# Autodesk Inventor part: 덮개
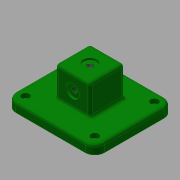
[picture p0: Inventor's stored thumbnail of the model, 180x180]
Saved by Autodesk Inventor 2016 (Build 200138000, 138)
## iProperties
Created: 2017-08
Part Number: 덮개
Material: 알루미늄 6061
Document SubType Name: Modeling
Designer: mduedu
Density: 1 g/cm^3
Appearance: 진녹색
Author: mduedu
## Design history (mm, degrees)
sketch "스케치1"
  geometry: L1 (46, -41)-(-46, -41); L2 (-46, -41)-(-46, 41); L3 (-46, 41)-(46, 41); L4 (46, 41)-(46, -41); 1 further point
  constraints: 8 end point, 2 parallel, 1 horizontal, 1 perpendicular
  dimensions: "d0" = 92 distance of L2.end L3.end; "d2" = 82 distance of L1.end L2.end; "d3" = 41 distance from line of L3 point (0, 0) (= 0.5 x d2); "d4" = 46 distance from line of point (0, 0) L4 (= 0.5 x d0)
extrude "돌출1" new body sketch "스케치1" distance "d5" = 10; taper "d6" = 0 deg
sketch "스케치2"
  geometry: L1 (-18, -18)-(18, -18); L2 (18, -18)-(18, 18); L3 (18, 18)-(-18, 18); L4 (-18, 18)-(-18, -18); L5 (-18, -18)-(18, 18); L6 (18, -18)-(-18, 18); 1 further point
  constraints: 12 end point, 2 midpoint, 2 parallel, 2 perpendicular, 1 horizontal
  dimensions: "d7" = 36 distance of L2.end L3.end
extrude "돌출2" join sketch "스케치2" distance "d9" = 32; taper "d10" = 0 deg
sketch "스케치3"
  geometry: L1 (-26, -26)-(26, -26); L2 (26, -26)-(26, 26); L3 (26, 26)-(-26, 26); L4 (-26, 26)-(-26, -26); L5 (-26, -26)-(26, 26); L6 (26, -26)-(-26, 26); 1 further point
  constraints: 12 end point, 2 midpoint, 2 parallel, 2 perpendicular, 1 horizontal
  dimensions: "d11" = 52 distance of L3.end L2.end
extrude "돌출3" join sketch "스케치3" distance "d12" = 6; taper "d13" = 0 deg
sketch "스케치4"
  geometry: L1 (-17, -17)-(17, -17); L2 (17, -17)-(17, 17); L3 (17, 17)-(-17, 17); L4 (-17, 17)-(-17, -17); L5 (-17, -17)-(17, 17); L6 (17, -17)-(-17, 17); 1 further point
  constraints: 12 end point, 2 midpoint, 2 parallel, 2 perpendicular, 1 horizontal
  dimensions: "d14" = 34 distance of L2.end L3.end
extrude "돌출4" cut sketch "스케치4" distance "d16" = 5; taper "d17" = 0 deg
sketch "스케치5"
  geometry: C1 r 9 at (0, 0); 1 further point
  constraints: 1 centre point, 1 coincident
  dimensions: "d18" = 18 diameter of C1
extrude "돌출5" cut sketch "스케치5" distance "d19" = 34; taper "d20" = 0 deg
sketch "스케치6"
  geometry: 2 further points
  constraints: 1 coincident
hole "구멍1" sketch "스케치6" at (0, 0) diameter "d21" = 5.917; stored, may be unused: countersink angle "d25" = 90 deg, drill point angle "d27" = 118 deg; dims "d22" = 6, "d23" = 14, "d24" = 2, "d26" = 8
sketch "스케치7"
  geometry: L1 (-28, -10)-(64, -10) reference; 3 further points
  constraints: 1 midpoint, 1 vertical alignment
  dimensions: "d47" = 26 distance from line of point (18, 16) L1
hole "구멍2" sketch "스케치7" at (18, 16) diameter "d29" = 5.917; stored, may be unused: countersink angle "d33" = 90 deg, drill point angle "d35" = 118 deg; dims "d30" = 6, "d31" = 14, "d32" = 2, "d34" = 8
fillet "모깎기1" dims "d36" = 10
fillet "모깎기2" dims "d37" = 3
fillet "모깎기3" dims "d38" = 3
fillet "모깎기4" dims "d39" = 3
fillet "모깎기5" dims "d40" = 3
chamfer "모따기1" distance "d41" = 1; stored, may be unused: second distance "d42" = 2, angle "d43" = 45 deg
fillet "모깎기6" dims "d44" = 3
fillet "모깎기7" dims "d45" = 3
fillet "모깎기8" dims "d46" = 3
sketch "스케치8"
  geometry: A1 r 10 centre (-36, -31) between (-46, -31) and (-36, -41) reference; A2 r 10 centre (-36, 31) between (-36, 41) and (-46, 31) reference; A3 r 10 centre (36, 31) between (46, 31) and (36, 41) reference; A4 r 10 centre (36, -31) between (36, -41) and (46, -31) reference; 5 further points
  constraints: 4 coincident
sketch "스케치9"
  geometry: 4 further points
  constraints: 4 other
hole "구멍3" sketch "스케치9" at (-36, -31), (-36, 31), (36, 31), (36, -31) diameter "d48" = 4.5; stored, may be unused: countersink angle "d52" = 90 deg, drill point angle "d54" = 0 deg; dims "d49" = 6, "d50" = 8, "d51" = 4.6, "d53" = 8
node "솔리드1"
